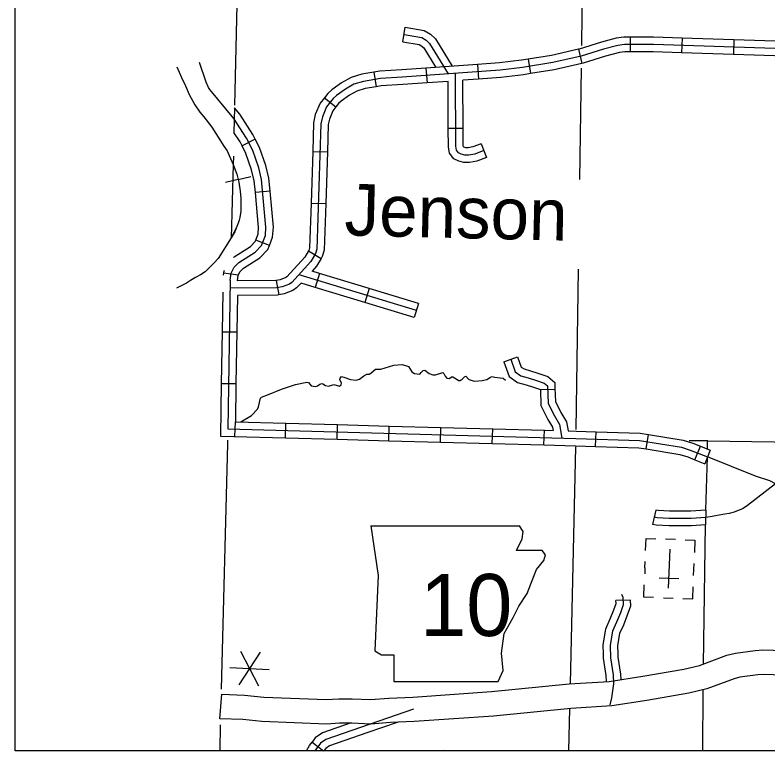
# Model space of a CAD drawing. Extents: x 1370567 to 1373900, y 377514 to 379648.
# Drawn here: x 1371518.1 to 1371737.8, y 377817.6 to 378032.3 of the extents above; entities that cross this region are included whole.
import ezdxf

# ---------------------------------------------------------------- set-up
doc = ezdxf.new("R2010")
doc.units = 0
doc.layers.add('Default', color=7, linetype='Continuous')
doc.layers.add('Survey Symbols', color=7, linetype='Continuous')

msp = doc.modelspace()

# ---------------------------------------------------------------- linework, layer by layer
at = {"layer": 'Default'}
for p, q in [((1371631.26, 378024.53), (1371631.99, 378028.75)), ((1371697.62, 378025.91), (1371697.61, 378021.62)), ((1371712.77, 378025.62), (1371712.63, 378021.34)), ((1371727.85, 378025.12), (1371727.71, 378020.84)), ((1371682.55, 378022.34), (1371683.49, 378018.16)), ((1371653.07, 378017.9), (1371653.38, 378013.63)), ((1371667.88, 378019.46), (1371668.57, 378015.23)), ((1371622.8, 378015.63), (1371623.49, 378011.4)), ((1371638.03, 378016.8), (1371638.34, 378012.53)), ((1371608.39, 378008.18), (1371611.77, 378005.54)), ((1371648.83, 377999.22), (1371644.54, 377999.21)), ((1371588.2, 377996.1), (1371584.38, 377994.14)), ((1371654.17, 377994.77), (1371655.72, 377990.78)), ((1371604.97, 377992.51), (1371609.25, 377992.37)), ((1371583.24, 377984.31), (1371586.9, 377985.2)), ((1371583.24, 377984.31), (1371579.57, 377983.42)), ((1371592.52, 377980.93), (1371588.25, 377980.53)), ((1371604.49, 377977.43), (1371608.77, 377977.29)), ((1371592.34, 377965.08), (1371588.34, 377966.62)), ((1371603.74, 377963.48), (1371607.44, 377961.32)), ((1371583.27, 377956.37), (1371579.03, 377956.95)), ((1371606.98, 377956.94), (1371605.73, 377952.84)), ((1371594.27, 377954.85), (1371595.08, 377950.64)), ((1371621.41, 377952.56), (1371620.17, 377948.46)), ((1371635.85, 377948.18), (1371634.6, 377944.08)), ((1371578.54, 377939.92), (1371582.83, 377939.85)), ((1371660.73, 377931.15), (1371664.76, 377932.61)), ((1371578.3, 377924.83), (1371582.59, 377924.76)), ((1371671.4, 377923.04), (1371675.68, 377923.18)), ((1371582.29, 377909.32), (1371582.41, 377913.6)), ((1371597.06, 377908.92), (1371597.17, 377913.2)), ((1371612.14, 377908.51), (1371612.25, 377912.8)), ((1371627.22, 377908.11), (1371627.33, 377912.39)), ((1371642.3, 377907.7), (1371642.41, 377911.99)), ((1371657.38, 377907.3), (1371657.49, 377911.58)), ((1371672.46, 377906.89), (1371672.57, 377911.17)), ((1371687.53, 377906.45), (1371687.67, 377910.73)), ((1371702.3, 377905.68), (1371702.98, 377909.92)), ((1371716.51, 377902.51), (1371718.09, 377906.49)), ((1371705.09, 377887.86), (1371704.13, 377883.69)), ((1371719.72, 377887.84), (1371719.63, 377883.54)), ((1371621.9, 377883.3), (1371624.07, 377868.8)), ((1371666.37, 377881.61), (1371665.36, 377883.28)), ((1371666.12, 377879.43), (1371666.37, 377881.61)), ((1371664.43, 377876.05), (1371666.12, 377879.43)), ((1371710.8, 377879.27), (1371707.94, 377879.38)), ((1371671.92, 377876.05), (1371664.43, 377876.05)), ((1371672.89, 377874.84), (1371671.92, 377876.05)), ((1371708.84, 377865.05), (1371709.28, 377876.47)), ((1371670.23, 377870.49), (1371672.41, 377873.15)), ((1371672.41, 377873.15), (1371672.89, 377874.84)), ((1371701.92, 377871.03), (1371701.99, 377872.84)), ((1371701.92, 377871.03), (1371701.86, 377869.27)), ((1371709.06, 377870.76), (1371709.06, 377870.76)), ((1371709.06, 377870.76), (1371709.06, 377870.76)), ((1371716.13, 377868.73), (1371716.27, 377872.29)), ((1371624.07, 377868.8), (1371623.1, 377846.8)), ((1371669.02, 377867.35), (1371670.23, 377870.49)), ((1371667.57, 377863.48), (1371669.02, 377867.35)), ((1371711.81, 377867.79), (1371706.07, 377868.01)), ((1371665.16, 377859.86), (1371667.57, 377863.48)), ((1371707.29, 377862.25), (1371710.15, 377862.14)), ((1371663.47, 377856.47), (1371665.16, 377859.86)), ((1371697.74, 377861.56), (1371693.46, 377861.42)), ((1371660.81, 377851.88), (1371663.47, 377856.47)), ((1371660.08, 377846.08), (1371660.81, 377851.88)), ((1371583.94, 377846.71), (1371589.13, 377836.53)), ((1371623.1, 377846.8), (1371625.04, 377845.6)), ((1371589.65, 377846.41), (1371583.42, 377836.83)), ((1371625.04, 377845.6), (1371628.66, 377845.6)), ((1371628.66, 377845.6), (1371628.66, 377837.86)), ((1371660.57, 377841), (1371660.08, 377846.08)), ((1371580.83, 377841.92), (1371592.24, 377841.32)), ((1371659.12, 377837.86), (1371660.57, 377841)), ((1371628.66, 377837.86), (1371659.12, 377837.86)), ((1371577.83, 377826.97), (1371578.44, 377834.09)), ((1371604.82, 377820.13), (1371608.17, 377817.56)), ((1371643.76, 377817.56), (1371643.52, 377817.72))]:
    msp.add_line(p, q, dxfattribs=at)
for points in [[(1371684.93, 378105.24), (1371683.82, 378059.8), (1371683.36, 378023.42)], [(1371583.36, 378056.58), (1371582.29, 378010.07)], [(1371631.62, 378026.64), (1371636.77, 378025.76), (1371638.1, 378025.02), (1371639.07, 378024.06), (1371644.52, 378015.13)], [(1371631.99, 378028.75), (1371637.5, 378027.81), (1371639.39, 378026.75), (1371640.76, 378025.41), (1371645.67, 378017.36)], [(1371631.26, 378024.53), (1371636.05, 378023.71), (1371636.8, 378023.29), (1371637.38, 378022.72), (1371640.87, 378017.01)], [(1371697.62, 378025.91), (1371695.74, 378025.91), (1371693.55, 378025.55), (1371689.26, 378024.41), (1371682.77, 378022.39), (1371682.55, 378022.34)], [(1371712.77, 378025.62), (1371704.44, 378025.89), (1371697.62, 378025.91)], [(1371727.85, 378025.12), (1371712.77, 378025.62)], [(1371742.93, 378024.62), (1371727.85, 378025.12)], [(1371807.75, 378020.34), (1371704.4, 378023.75), (1371695.91, 378023.77), (1371694, 378023.45), (1371689.85, 378022.35), (1371683.32, 378020.32), (1371675.04, 378018.46), (1371666.18, 378017.01), (1371659.68, 378016.24), (1371631.12, 378014.15), (1371624.75, 378013.78), (1371619.83, 378012.98), (1371617.01, 378012.13), (1371614.55, 378010.71), (1371611.93, 378008.84), (1371610.95, 378007.96), (1371609.02, 378005.5), (1371607.79, 378002.63), (1371607.37, 378000.62), (1371606.21, 377964.04), (1371605.78, 377962.72), (1371604.39, 377960.36), (1371598.85, 377954.29), (1371598.17, 377953.82), (1371596.1, 377953.01), (1371594.45, 377952.7), (1371580.82, 377952.57)], [(1371682.55, 378022.34), (1371674.63, 378020.56), (1371667.88, 378019.46)], [(1371697.61, 378021.62), (1371696.09, 378021.63), (1371694.46, 378021.35), (1371690.45, 378020.29), (1371683.87, 378018.25), (1371683.49, 378018.16)], [(1371712.63, 378021.34), (1371704.36, 378021.61), (1371697.61, 378021.62)], [(1371727.71, 378020.84), (1371712.63, 378021.34)], [(1371742.78, 378020.34), (1371727.71, 378020.84)], [(1371580.92, 377954.97), (1371581.2, 377957), (1371582.03, 377958.7), (1371583.41, 377960.12), (1371588.21, 377963.15), (1371590.05, 377965.1), (1371591.17, 377968.01), (1371591.34, 377970.38), (1371590.06, 377984.33), (1371589.22, 377987.77), (1371587.47, 377992.81), (1371585.63, 377996.41), (1371581.94, 378002.12), (1371574.95, 378010.59), (1371574.58, 378011.2), (1371573.88, 378012.77), (1371571.95, 378018.46)], [(1371653.07, 378017.9), (1371638.03, 378016.8)], [(1371667.88, 378019.46), (1371665.88, 378019.13), (1371659.48, 378018.37), (1371653.07, 378017.9)], [(1371683.49, 378018.16), (1371675.45, 378016.35), (1371668.57, 378015.23)], [(1371565.35, 378017.24), (1371566.72, 378014.13), (1371567.88, 378011.64), (1371568.95, 378009.18), (1371570.6, 378006.12), (1371572.08, 378003.98), (1371573.19, 378002.6), (1371575.5, 377999.59), (1371579.03, 377994.09), (1371579.97, 377992.68), (1371580.59, 377991.38), (1371581.76, 377988.74), (1371582.86, 377985.85), (1371583.42, 377983.55), (1371583.79, 377980.96), (1371583.99, 377978.91), (1371584.03, 377976.97), (1371584.01, 377975.06), (1371583.7, 377973.25), (1371583.49, 377972.45), (1371583.19, 377971.62), (1371582.64, 377970.11), (1371582.22, 377969.05), (1371581.79, 377968.28), (1371581.21, 377967.33), (1371577.43, 377961.3), (1371576.26, 377960.02), (1371574.8, 377958.57), (1371573.56, 377957.37), (1371572.24, 377956.52), (1371570.76, 377955.7), (1371569.35, 377954.9), (1371568.11, 377954.11), (1371565.25, 377952.63)], [(1371622.8, 378015.63), (1371619.34, 378015.07), (1371616.16, 378014.11), (1371613.39, 378012.52), (1371610.59, 378010.52), (1371609.38, 378009.44), (1371608.39, 378008.18)], [(1371638.03, 378016.8), (1371630.98, 378016.29), (1371624.52, 378015.91), (1371622.8, 378015.63)], [(1371683.27, 378016.84), (1371682.81, 377984.34)], [(1371654.95, 377992.77), (1371652.3, 377991.74), (1371650.53, 377991.45), (1371649.36, 377991.45), (1371648.33, 377991.74), (1371647.52, 377992.11), (1371646.93, 377992.92), (1371646.71, 377994.1), (1371646.61, 378015.28)], [(1371653.38, 378013.63), (1371648.77, 378013.29)], [(1371668.57, 378015.23), (1371666.48, 378014.89), (1371659.88, 378014.1), (1371653.38, 378013.63)], [(1371623.49, 378011.4), (1371620.31, 378010.88), (1371617.87, 378010.15), (1371615.71, 378008.91), (1371613.27, 378007.16), (1371612.51, 378006.49), (1371611.77, 378005.54)], [(1371638.34, 378012.53), (1371631.26, 378012.01), (1371624.99, 378011.65), (1371623.49, 378011.4)], [(1371644.48, 378012.98), (1371638.34, 378012.53)], [(1371644.54, 377999.21), (1371644.48, 378012.98)], [(1371648.83, 377999.22), (1371648.77, 378013.29)], [(1371582.29, 378010.07), (1371582.19, 378006.04)], [(1371608.39, 378008.18), (1371607.16, 378006.61), (1371605.73, 378003.28), (1371605.23, 378000.88), (1371604.97, 377992.51)], [(1371588.2, 377996.1), (1371587.49, 377997.48), (1371583.67, 378003.39), (1371582.17, 378005.21), (1371582.01, 377998.07)], [(1371611.77, 378005.54), (1371610.88, 378004.4), (1371609.84, 378001.98), (1371609.5, 378000.37), (1371609.25, 377992.37)], [(1371584.38, 377994.14), (1371583.77, 377995.34), (1371582.01, 377998.07)], [(1371655.72, 377990.78), (1371652.87, 377989.67), (1371650.71, 377989.31), (1371649.06, 377989.31), (1371647.58, 377989.73), (1371646.12, 377990.39), (1371644.91, 377992.05), (1371644.57, 377993.9), (1371644.54, 377999.21)], [(1371654.17, 377994.77), (1371651.73, 377993.82), (1371650.36, 377993.59), (1371649.66, 377993.59), (1371649.07, 377993.76), (1371648.94, 377993.82), (1371648.85, 377994.3), (1371648.83, 377999.22)], [(1371592.52, 377980.93), (1371592.17, 377984.68), (1371591.28, 377988.37), (1371589.45, 377993.65), (1371588.2, 377996.1)], [(1371588.25, 377980.53), (1371587.94, 377983.97), (1371587.16, 377987.16), (1371585.5, 377991.96), (1371584.38, 377994.14)], [(1371604.97, 377992.51), (1371604.49, 377977.43)], [(1371609.25, 377992.37), (1371608.77, 377977.29)], [(1371581.84, 377991.14), (1371581.76, 377988.74), (1371581.21, 377967.35)], [(1371581.76, 377988.74), (1371582.86, 377985.85), (1371583.42, 377983.55), (1371583.79, 377980.96), (1371583.99, 377978.91), (1371584.03, 377976.97), (1371584.01, 377975.06), (1371583.7, 377973.25), (1371583.49, 377972.45), (1371583.19, 377971.62), (1371582.64, 377970.11), (1371581.21, 377967.33)], [(1371588.34, 377966.62), (1371589.06, 377968.48), (1371589.19, 377970.35), (1371588.25, 377980.53)], [(1371592.34, 377965.08), (1371593.29, 377967.54), (1371593.49, 377970.4), (1371592.52, 377980.93)], [(1371604.49, 377977.43), (1371604.08, 377964.42), (1371603.81, 377963.61), (1371603.74, 377963.48)], [(1371608.77, 377977.29), (1371608.34, 377963.67), (1371607.74, 377961.84), (1371607.44, 377961.32)], [(1371581.82, 377961.56), (1371582.05, 377961.79), (1371586.84, 377964.82), (1371588.2, 377966.27), (1371588.34, 377966.62)], [(1371583.05, 377954.73), (1371583.27, 377956.37), (1371583.8, 377957.45), (1371584.76, 377958.44), (1371589.59, 377961.49), (1371591.9, 377963.94), (1371592.34, 377965.08)], [(1371603.74, 377963.48), (1371602.66, 377961.63), (1371597.43, 377955.92), (1371597.16, 377955.73), (1371595.5, 377955.08), (1371594.27, 377954.85)], [(1371607.44, 377961.32), (1371606.13, 377959.08), (1371604.79, 377957.61)], [(1371578.95, 377956.38), (1371579.12, 377957.63), (1371579.26, 377957.91)], [(1371635.23, 377946.13), (1371600.98, 377956.53)], [(1371606.98, 377956.94), (1371604.79, 377957.61)], [(1371621.41, 377952.56), (1371606.98, 377956.94)], [(1371682.44, 377958.13), (1371681.78, 377911.34)], [(1371580.92, 377954.97), (1371580.23, 377911.52), (1371681.74, 377908.78), (1371700.3, 377908.18), (1371712.59, 377906.2), (1371715.12, 377905.36), (1371720.16, 377903.37)], [(1371594.27, 377954.85), (1371594.24, 377954.84), (1371583.05, 377954.73)], [(1371601.58, 377954.1), (1371600.27, 377952.67), (1371599.18, 377951.92), (1371596.69, 377950.95), (1371595.08, 377950.64)], [(1371605.73, 377952.84), (1371601.58, 377954.1)], [(1371620.17, 377948.46), (1371605.73, 377952.84)], [(1371635.85, 377948.18), (1371621.41, 377952.56)], [(1371578.72, 377951.48), (1371578.54, 377939.92)], [(1371582.99, 377950.45), (1371582.83, 377939.85)], [(1371595.08, 377950.64), (1371594.66, 377950.56), (1371582.99, 377950.45)], [(1371634.6, 377944.08), (1371620.17, 377948.46)], [(1371578.54, 377939.92), (1371578.3, 377924.83)], [(1371582.83, 377939.85), (1371582.59, 377924.76)], [(1371664.76, 377932.61), (1371665.85, 377929.6), (1371666.68, 377929.03), (1371668.51, 377928.46), (1371670.69, 377927.79), (1371673.58, 377926.83), (1371675.62, 377925.13), (1371675.67, 377923.39)], [(1371619.92, 377927.07), (1371620.74, 377927.52), (1371621.42, 377927.56), (1371621.91, 377927.79), (1371622.67, 377928.46), (1371623.28, 377928.99), (1371624.83, 377929.02), (1371628.64, 377930.11), (1371631.09, 377930.33), (1371632.93, 377929.76), (1371633.9, 377928.24), (1371634.65, 377927.71), (1371636.2, 377927.48), (1371636.64, 377928.03), (1371637.23, 377928.61), (1371637.72, 377928.65), (1371638.96, 377927.76), (1371640.03, 377927.29), (1371640.8, 377927.34), (1371642.96, 377927.98), (1371643.22, 377927.69), (1371643.64, 377926.9), (1371644.08, 377926.34), (1371644.91, 377926.24), (1371645.52, 377926.79), (1371645.84, 377926.77), (1371647.6, 377925.69), (1371648.03, 377925.67), (1371648.62, 377926.02), (1371649.24, 377926.75), (1371649.64, 377926.98), (1371650.45, 377926.06)], [(1371660.73, 377931.15), (1371662.29, 377926.87), (1371664.77, 377925.13), (1371667.25, 377924.37), (1371669.38, 377923.71), (1371671.4, 377923.04)], [(1371662.75, 377931.88), (1371664.07, 377928.24), (1371665.73, 377927.08), (1371667.88, 377926.41), (1371670.03, 377925.75), (1371672.51, 377924.92), (1371673.51, 377924.1), (1371673.67, 377918.96), (1371675.49, 377915.32), (1371676.98, 377912.83), (1371677.64, 377908.89)], [(1371584.05, 377913.56), (1371587.13, 377915.47), (1371588.87, 377917.35), (1371589.14, 377917.98), (1371589.73, 377920.48), (1371590.03, 377920.8), (1371592.08, 377921.63), (1371595.88, 377923.16), (1371599.91, 377924.46), (1371603.27, 377925.15), (1371603.73, 377925.07), (1371604.14, 377924.62), (1371604.52, 377924.08), (1371605.89, 377923.91), (1371606.37, 377924.09), (1371607.02, 377924.64), (1371607.65, 377924.83), (1371607.94, 377924.66), (1371608.69, 377924.19), (1371609.61, 377923.98), (1371611.14, 377924.49), (1371612.75, 377924.06), (1371613.28, 377924.39), (1371613.33, 377925.01), (1371612.91, 377925.86), (1371612.96, 377926.35), (1371613.41, 377926.81), (1371614.1, 377926.6), (1371615.97, 377925.92), (1371617.63, 377925.78), (1371618.62, 377926.08), (1371619.92, 377927.07)], [(1371650.45, 377926.06), (1371651.09, 377925.72), (1371652.23, 377925.52), (1371654.46, 377925.67), (1371655.83, 377925.98), (1371656.84, 377926.68), (1371657.32, 377926.81), (1371658.01, 377926.65), (1371660.53, 377926.32), (1371661.23, 377925.77)], [(1371578.3, 377924.83), (1371578.06, 377909.43), (1371581.98, 377909.33)], [(1371582.59, 377924.76), (1371582.41, 377913.6)], [(1371675.67, 377923.39), (1371675.8, 377919.5), (1371677.37, 377916.35), (1371679.03, 377913.59), (1371679.47, 377910.99)], [(1371671.4, 377923.04), (1371671.55, 377918.42), (1371673.61, 377914.28), (1371674.94, 377912.08), (1371675.1, 377911.11)], [(1371582.41, 377913.6), (1371597.17, 377913.2)], [(1371597.17, 377913.2), (1371612.25, 377912.8)], [(1371612.25, 377912.8), (1371627.33, 377912.39)], [(1371627.33, 377912.39), (1371642.41, 377911.99)], [(1371642.41, 377911.99), (1371657.49, 377911.58)], [(1371657.49, 377911.58), (1371672.57, 377911.17)], [(1371672.57, 377911.17), (1371675.1, 377911.11)], [(1371679.47, 377910.99), (1371681.81, 377910.93), (1371687.67, 377910.73)], [(1371687.67, 377910.73), (1371700.5, 377910.31), (1371702.98, 377909.92)], [(1371580.15, 377908.26), (1371580.12, 377907.21)], [(1371581.98, 377909.33), (1371597.06, 377908.92)], [(1371597.06, 377908.92), (1371612.14, 377908.51)], [(1371612.14, 377908.51), (1371627.22, 377908.11)], [(1371627.22, 377908.11), (1371642.3, 377907.7)], [(1371702.98, 377909.92), (1371713.1, 377908.29), (1371715.85, 377907.38), (1371718.09, 377906.49)], [(1371720.29, 377908.05), (1371714.86, 377908.08)], [(1371720.16, 377905.67), (1371720.16, 377908.05), (1371784.94, 377907.09)], [(1371580.12, 377907.21), (1371578.27, 377835.62)], [(1371642.3, 377907.7), (1371657.38, 377907.3)], [(1371657.38, 377907.3), (1371672.46, 377906.89)], [(1371672.46, 377906.89), (1371681.68, 377906.64), (1371687.53, 377906.45)], [(1371681.69, 377906.32), (1371680.13, 377837.14)], [(1371687.53, 377906.45), (1371700.09, 377906.04), (1371702.3, 377905.68)], [(1371718.09, 377906.49), (1371720.94, 377905.36), (1371719.37, 377901.38)], [(1371702.3, 377905.68), (1371712.08, 377904.11), (1371714.39, 377903.35), (1371716.51, 377902.51)], [(1371716.51, 377902.51), (1371719.37, 377901.38)], [(1371719.72, 377887.84), (1371720.16, 377903.37)], [(1371750.89, 377893.97), (1371746.29, 377894.28), (1371744.95, 377894.53), (1371743.83, 377894.75), (1371742.43, 377894.97), (1371741.69, 377895.05), (1371740.83, 377895.16), (1371739.97, 377895.56), (1371738.37, 377896.35), (1371734.21, 377897.78), (1371720.16, 377903.37)], [(1371739.97, 377895.56), (1371731.84, 377889.16), (1371730.55, 377888.33), (1371727.92, 377887.23), (1371726.45, 377886.87), (1371725.26, 377886.69), (1371723.57, 377886.4), (1371722.52, 377886.22), (1371721.52, 377885.98), (1371719.66, 377885.69)], [(1371719.72, 377887.84), (1371715.35, 377887.57), (1371709.06, 377887.57), (1371705.77, 377887.71), (1371705.09, 377887.86)], [(1371719.66, 377885.69), (1371715.42, 377885.43), (1371709.02, 377885.43), (1371705.48, 377885.57), (1371704.53, 377885.79)], [(1371621.9, 377883.3), (1371665.36, 377883.28)], [(1371719.63, 377883.54), (1371715.48, 377883.28), (1371708.97, 377883.28), (1371705.2, 377883.44), (1371704.13, 377883.69)], [(1371718.96, 377842.81), (1371719.63, 377883.54)], [(1371702.11, 377876.02), (1371702.25, 377879.59), (1371705.1, 377879.48)], [(1371713.67, 377879.16), (1371716.52, 377879.05), (1371716.39, 377875.48)], [(1371704.45, 377862.35), (1371701.6, 377862.46), (1371701.73, 377866.03)], [(1371713.02, 377862.03), (1371715.87, 377861.92), (1371716.01, 377865.49)], [(1371691.8, 377831.03), (1371692.22, 377833.05), (1371692.87, 377837.1), (1371692.75, 377839.75), (1371691.99, 377844.78), (1371691.91, 377848.32), (1371692.54, 377852.58), (1371693.75, 377855.24), (1371694.84, 377857.99), (1371695.64, 377860.28), (1371695.57, 377862.38), (1371695.17, 377863.23)], [(1371689.82, 377845.91), (1371689.76, 377848.45), (1371690.46, 377853.2), (1371691.78, 377856.08), (1371692.83, 377858.74), (1371693.49, 377860.61), (1371693.46, 377861.42)], [(1371694.1, 377846.01), (1371694.05, 377848.19), (1371694.61, 377851.97), (1371695.72, 377854.4), (1371696.85, 377857.24), (1371697.8, 377859.95), (1371697.74, 377861.56)], [(1371578.44, 377834.09), (1371585.07, 377833.82), (1371590.67, 377833.25), (1371608.93, 377832.55), (1371612.59, 377832.77), (1371616.5, 377832.79), (1371621.85, 377832.55), (1371627.2, 377832.97), (1371634.16, 377833.3), (1371657.14, 377834.86), (1371679.76, 377837.12), (1371691.52, 377837.84), (1371701.29, 377839.36), (1371713.29, 377841.38), (1371717.84, 377842.52), (1371725.84, 377845.5), (1371728.33, 377846.08), (1371734.1, 377846.9), (1371736.27, 377847.05), (1371760.13, 377846.27), (1371770.17, 377845.95)], [(1371690.69, 377837.79), (1371690.62, 377839.54), (1371689.85, 377844.59), (1371689.82, 377845.91)], [(1371694.96, 377838.37), (1371694.89, 377839.95), (1371694.13, 377844.97), (1371694.1, 377846.01)], [(1371769.79, 377838.82), (1371759.9, 377839.13), (1371736.39, 377839.9), (1371734.84, 377839.79), (1371729.65, 377839.06), (1371727.92, 377838.65), (1371719.96, 377835.69), (1371714.76, 377834.38), (1371702.43, 377832.31), (1371692.29, 377830.73), (1371680.34, 377829.99), (1371657.74, 377827.74), (1371634.57, 377826.16), (1371627.65, 377825.84), (1371621.97, 377825.39), (1371616.35, 377825.65), (1371612.83, 377825.63), (1371609.01, 377825.4), (1371590.18, 377826.12), (1371584.57, 377826.69), (1371577.83, 377826.97)], [(1371718.79, 377817.56), (1371718.88, 377835.29)], [(1371634.36, 377829.73), (1371608.82, 377820.94), (1371607.26, 377819.79), (1371605.87, 377817.98), (1371605.64, 377817.56)], [(1371679.94, 377829.97), (1371679.57, 377817.56)], [(1371578.02, 377825.21), (1371577.85, 377817.56)], [(1371615.9, 377825.65), (1371607.81, 377822.86), (1371605.74, 377821.34), (1371604.82, 377820.13)], [(1371629.95, 377825.95), (1371620.8, 377822.8)], [(1371620.8, 377822.8), (1371609.83, 377819.02), (1371608.77, 377818.25), (1371608.24, 377817.56)], [(1371603.21, 377817.56), (1371604.06, 377819.15), (1371604.82, 377820.13)], [(1371643.41, 377817.56), (1371643.52, 377817.72)]]:
    msp.add_lwpolyline(points, dxfattribs=at)
at = {"layer": 'Survey Symbols'}
msp.add_lwpolyline([(1371518.13, 378743.2), (1373025.55, 378743.2), (1373025.55, 377817.56), (1371518.13, 377817.56)], close=True, dxfattribs=at)
msp.add_lwpolyline([(1371518.13, 378743.2), (1373025.55, 378743.2), (1373025.55, 377817.56), (1371518.13, 377817.56)], close=True, dxfattribs=at)
msp.add_lwpolyline([(1371518.13, 378743.2), (1373025.55, 378743.2), (1373025.55, 377817.56), (1371518.13, 377817.56)], close=True, dxfattribs=at)

# ---------------------------------------------------------------- texts
at = {"layer": 'Default'}
msp.add_text('Jenson', height=15.086, rotation=358.6113, dxfattribs=at).set_placement((1371614.14, 377968.05))
msp.add_text('10', height=18.103, dxfattribs=at).set_placement((1371636.31, 377851.1))

doc.saveas('drawing.dxf')
